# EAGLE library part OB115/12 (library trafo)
TRANSFORMER 2 primary winding, 2 secondary windings, mounting holes BLOCK
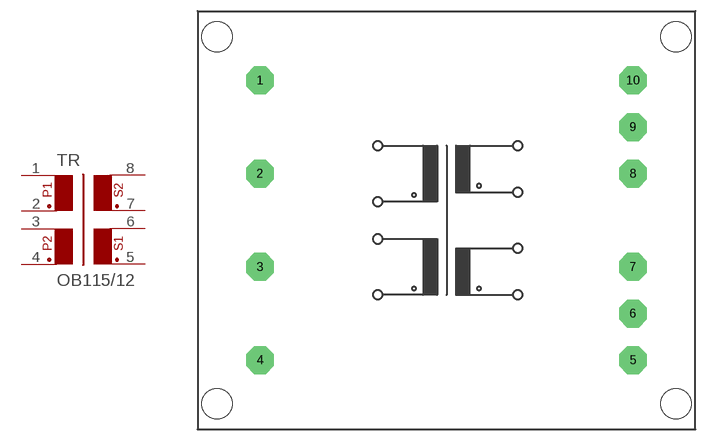
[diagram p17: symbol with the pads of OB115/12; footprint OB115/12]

Designator prefix TR

## OB115/12  [OB115/12]
1  1  pas
2  2  pas
3  3  pas
4  4  pas
5  5  pas
6  6  pas
7  7  pas
8  8  pas

## Footprint OB115/12 (pad centres in mm)
TRANSFORMER 2 primary winding, 2 secondary windings, mounting holes
drill 1.194 pad 3.81 octagon: 1 -25.4,19.05; 2 -25.4,6.35; 3 -25.4,-6.35; 4 -25.4,-19.05; 5 25.4,-19.05; 6 25.4,-12.7; 7 25.4,-6.35; 8 25.4,6.35; 9 25.4,12.7; 10 25.4,19.05
hole 4.115 at -31.267,24.994
hole 4.115 at 31.267,24.994
hole 4.115 at 31.267,-24.994
hole 4.115 at -31.267,-24.994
